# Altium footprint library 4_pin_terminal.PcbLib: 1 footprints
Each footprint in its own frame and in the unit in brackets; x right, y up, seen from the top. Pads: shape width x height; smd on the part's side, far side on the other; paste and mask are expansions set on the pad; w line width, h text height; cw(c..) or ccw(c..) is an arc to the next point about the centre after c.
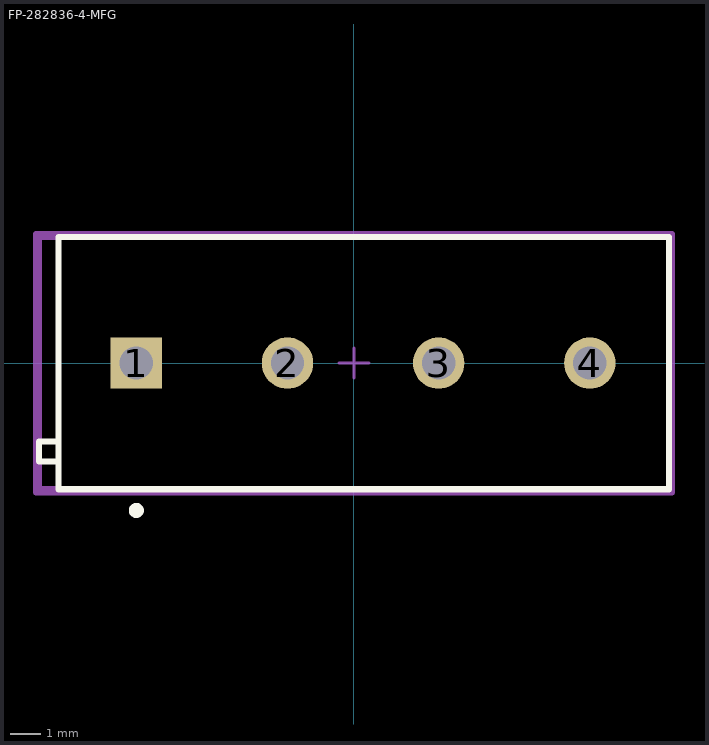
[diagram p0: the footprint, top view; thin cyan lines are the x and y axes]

## FP-282836-4-MFG [mm]
pads (4):
  rect 1.7x1.7 hole 1.1 paste-1000 mask+0: 1(-7.2,0)
  round 1.7 hole 1.1 paste-1000 mask+0: 2(-2.2,0) 3(2.8,0) 4(7.8,0)
Top Overlay:
  circle w0.25: c-7.2,-4.875 r0.125
  lines w0.2: -10.425,-3.25 -10.425,-2.6 -9.775,-2.6 -9.775,-3.25 -10.425,-3.25 ; -9.775,-4.175 -9.775,4.175 10.425,4.175 10.425,-4.175 -9.775,-4.175
Top Assembly:
  lines w0.2: -10.525,-4.275 -10.525,4.275 10.525,4.275 10.525,-4.275 -10.525,-4.275
  text ".Designator" at 0,0.188 h1
Top 3D Body:
  lines w0.2: -10.425,-4.175 -10.425,4.175 10.425,4.175 10.425,-4.175 -10.425,-4.175
Top Courtyard:
  lines w0.2: -10.525,-4.275 -10.525,4.275 10.525,4.275 10.525,-4.275 -10.525,-4.275
Top Component Center:
  lines w0.1: -0.5,0 0.5,0 ; 0,-0.5 0,0.5
3D body "Conn_TE_Connectivity_282836-4_eec.STEP": height 0.25, standoff 0, extent -10.525,-4.275 10.525,4.275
